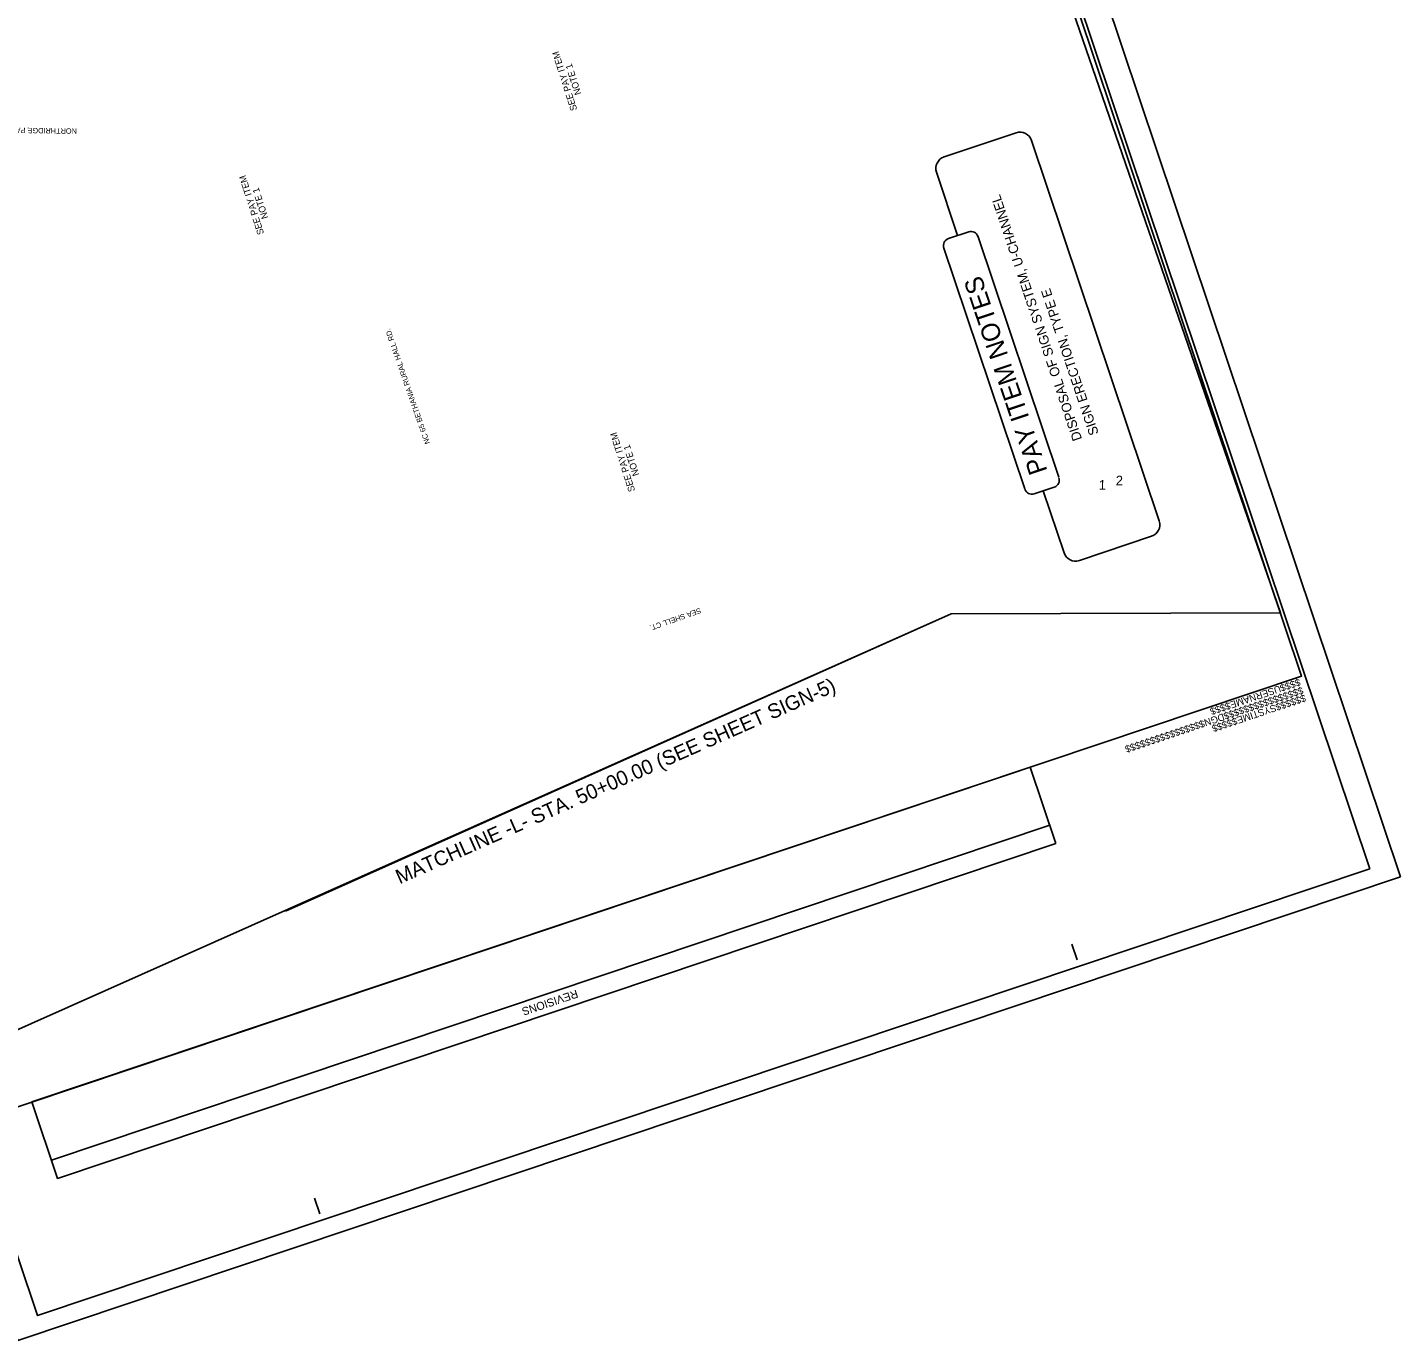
# Model space of a CAD drawing. Extents: x 1615436 to 1617010, y 903110 to 905055.
# Drawn here: x 1615979 to 1617010, y 903110 to 904096 of the extents above; entities that cross this region are included whole.
import ezdxf

# ---------------------------------------------------------------- set-up
doc = ezdxf.new("R2010")
doc.units = 0
for name, color, linetype in [('CTL Primary Horizontal and Vertical CELL', 7, 'Continuous'), ('CTL Primary Horizontal and Vertical Cogo Number', 7, 'Continuous'), ('Default', 7, 'Continuous'), ('Exist DTM Regular Point Cogo Number', 7, 'Continuous'), ('Exist Roads Curbs Cogo Number', 7, 'Continuous'), ('Exist Roads Curbs Cogo Point CELL', 7, 'Continuous'), ('Exist Structure Minor Pipes RCP 15 Inch Cogo Number', 7, 'Continuous'), ('Exist Structure Minor Pipes RCP 15 Inch Cogo Point CELL', 7, 'Continuous'), ('Exist Utilities Sanitary Sewer Manhole CELL', 7, 'Continuous'), ('Exist Utilities Sanitary Sewer Manhole Cogo Number', 7, 'Continuous')]:
    doc.layers.add(name, color=color, linetype=linetype)

msp = doc.modelspace()

# ---------------------------------------------------------------- linework, layer by layer
at = {"layer": 'CTL Primary Horizontal and Vertical CELL'}
msp.add_lwpolyline([(1616986.9, 903464.7), (1616457, 905044.2), (1615456.8, 904708.7), (1615986.6, 903129.2)], close=True, dxfattribs=at)
at = {"layer": 'CTL Primary Horizontal and Vertical Cogo Number'}
msp.add_lwpolyline([(1617010, 903458.7), (1616474.6, 905054.8), (1615436.4, 904706.6), (1615971.8, 903110.5)], close=True, dxfattribs=at)
at = {"layer": 'Exist DTM Regular Point Cogo Number'}
msp.add_lwpolyline([(1616672.6, 903656.2), (1616919.8, 903656.8), (1616590.6, 904611.2), (1616386.8, 904624.4), (1616334.8, 904821.6), (1616466, 905009.6), (1615641.1, 904732.9), (1615700, 904557.2), (1615560.3, 904510.3), (1615954.2, 903336.2)], close=True, dxfattribs=at)
at = {"layer": 'Exist Roads Curbs Cogo Point CELL'}
msp.add_line((1616172.6, 903432.8), (1616672.6, 903656.2), dxfattribs=at)
at = {"layer": 'Exist Structure Minor Pipes RCP 15 Inch Cogo Number'}
for p, q in [((1616935.7, 903609.4), (1616935.7, 903609.4)), ((1616767.2, 903396.3), (1616763.2, 903408.1)), ((1616198.4, 903205.5), (1616194.4, 903217.3))]:
    msp.add_line(p, q, dxfattribs=at)
msp.add_lwpolyline([(1615463.1, 904697.6), (1615940.2, 903275.5), (1616935.7, 903609.4), (1616458.6, 905031.5)], close=True, dxfattribs=at)
at = {"layer": 'Exist Structure Minor Pipes RCP 15 Inch Cogo Point CELL'}
msp.add_line((1616746.5, 903497.4), (1615996.9, 903246), dxfattribs=at)
msp.add_lwpolyline([(1616751.1, 903483.7), (1616001.5, 903232.2), (1615982.2, 903289.6), (1616731.8, 903541)], close=True, dxfattribs=at)
at = {"layer": 'Exist Utilities Sanitary Sewer Manhole Cogo Number'}
for p, q in [((1616721.4, 904017.4), (1616667.2, 903999.2)), ((1616828.8, 903725.9), (1616732.9, 904011.6)), ((1616677.4, 903940.2), (1616661.5, 903987.7)), ((1616685.7, 903943), (1616670.5, 903937.9)), ((1616750, 903751.3), (1616734.8, 903746.2)), ((1616757.3, 903701.9), (1616741.7, 903748.5)), ((1616823, 903714.4), (1616768.8, 903696.2))]:
    msp.add_line(p, q, dxfattribs=at)
for points in [[(1616753.3, 903758.7), (1616692.5, 903940)], [(1616727.8, 903750.1), (1616666.9, 903931.4)]]:
    msp.add_lwpolyline(points, dxfattribs=at)
for centre, radius, start, end in [((1616724.3, 904008.7), 9.09, 18.5432, 108.5432), ((1616670.1, 903990.6), 9.09, 108.5432, 198.5432), ((1616687.4, 903937.8), 5.45, 18.5432, 108.5432), ((1616672.2, 903932.7), 5.45, 108.5432, 198.5432), ((1616748.3, 903756.5), 5.45, 288.5432, 18.5432), ((1616733.1, 903751.4), 5.45, 198.5432, 288.5432), ((1616820.1, 903723), 9.09, 288.5432, 18.5432), ((1616765.9, 903704.8), 9.09, 198.5432, 288.5432)]:
    msp.add_arc(centre, radius, start, end, dxfattribs=at)

# ---------------------------------------------------------------- texts
at = {"layer": 'Default'}
for s, height, rotation, p in [('SEE PAY ITEM', 5, 107.7518, (1616391.8, 904034.8)), ('NOTE 1', 5, 107.7518, (1616394.9, 904046.7)), ('SEE PAY ITEM', 5, 107.7518, (1616156.7, 903941.7)), ('NOTE 1', 5, 107.7518, (1616159.8, 903953.6)), ('DISPOSAL OF SIGN SYSTEM, U-CHANNEL', 7.199, 108.5432, (1616770.9, 903787.4)), ('PAY ITEM NOTES', 13.866, 108.7254, (1616744.9, 903763.5)), ('SIGN ERECTION, TYPE E', 7.199, 108.5432, (1616783.4, 903791.6)), ('SEE PAY ITEM', 5, 107.7518, (1616435.3, 903748.7)), ('NOTE 1', 5, 107.7518, (1616438.4, 903760.6)), ('2', 7.2, 358.9459, (1616796.1, 903752.7)), ('1', 7.2, 358.9459, (1616783.3, 903749.4))]:
    msp.add_text(s, height=height, rotation=rotation, dxfattribs=at).set_placement(p)
at = {"layer": 'Exist Roads Curbs Cogo Number'}
msp.add_text('MATCHLINE -L- STA. 50+00.00 (SEE SHEET SIGN-5)', height=11, rotation=23.8606, dxfattribs=at).set_placement((1616258.4, 903453))
at = {"layer": 'Exist Structure Minor Pipes RCP 15 Inch Cogo Number'}
for s, p in [('$$$$USERNAME$$$$', (1616933.8, 903607.6)), ('$$$$$$$$$$$$$$$$DGN$$$$$$$$$$$$$$$$', (1616935.9, 903601.4)), ('$$$$$$SYSTIME$$$$$', (1616937.8, 903595.7))]:
    msp.add_text(s, height=5.25, rotation=198.5432, dxfattribs=at).set_placement(p)
at = {"layer": 'Exist Structure Minor Pipes RCP 15 Inch Cogo Point CELL'}
msp.add_text('REVISIONS', height=6, rotation=198.5432, dxfattribs=at).set_placement((1616391.1, 903374))
at = {"layer": 'Exist Utilities Sanitary Sewer Manhole CELL'}
for s, rotation, p in [('NORTHRIDGE PARK DR.', 179.239, (1616016.1, 904020.6)), ('NC 65 BETHANIA RURAL HALL RD.', 109.1948, (1616281.3, 903784.4)), ('SEA SHELL CT.', 199.404, (1616483.9, 903660.7))]:
    msp.add_text(s, height=4, rotation=rotation, dxfattribs=at).set_placement(p)

doc.saveas('drawing.dxf')
